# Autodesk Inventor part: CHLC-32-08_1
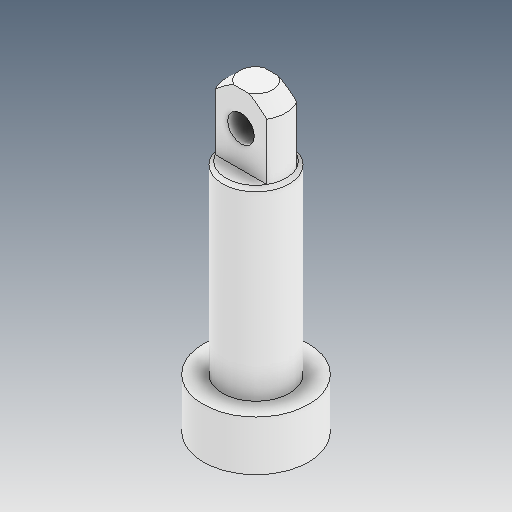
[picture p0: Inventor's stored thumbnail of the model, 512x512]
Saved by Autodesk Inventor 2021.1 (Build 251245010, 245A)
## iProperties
Created: 2021-05
Part Number: CHLC-32-08_1
Material: Ogólny
Document SubType Name: Modeling
Designer: user
Density: 1 g/cm^3
Appearance: Domyślna
Author: user
Revision Number: ÈÎºÎ
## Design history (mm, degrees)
feature "µ¹½Ç1"
node "Bryła1"
